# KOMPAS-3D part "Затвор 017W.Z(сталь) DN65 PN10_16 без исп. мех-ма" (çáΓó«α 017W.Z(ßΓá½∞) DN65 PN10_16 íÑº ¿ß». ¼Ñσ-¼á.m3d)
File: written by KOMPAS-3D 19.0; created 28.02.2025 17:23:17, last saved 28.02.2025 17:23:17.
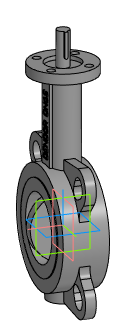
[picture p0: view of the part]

Document properties: Автор: Евгений; Полное имя файла: E:\Dendor Работа Сачек\3D для проекитирвщиков\1.5 Тип 017W.Z Сталь Затвор дисковый поворотный Межфланцевый\stp_Тип 017W.Z(сталь). Затвор без исполн. механизма\Затвор 017W.Z(сталь) DN65 PN10_16 без исп. мех-ма.m3d

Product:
- Part/product: Затвор 017W.Z(сталь) DN65 PN10_16 без исп. мех-ма

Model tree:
1. Операция без истории:1  (labels: Затвор 017W.Z(сталь) DN65 PN10_16 без исп. мех-ма)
